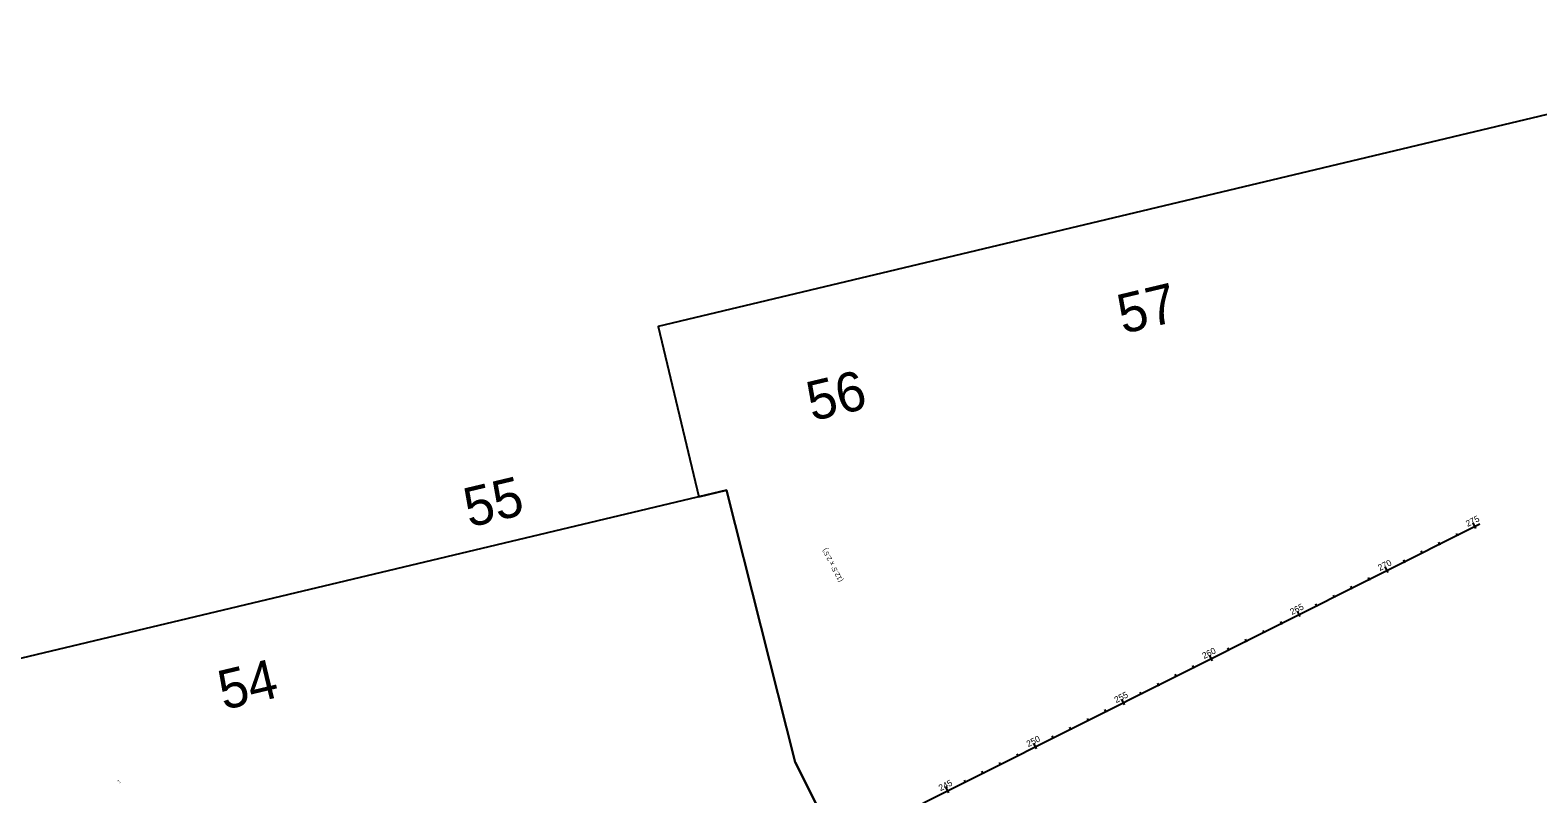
# Model space of a CAD drawing. Extents: x -5665 to 1997148, y 4 to 827579.
# Drawn here: x 1969802 to 1977472, y 804069 to 807957 of the extents above; entities that cross this region are included whole.
import ezdxf

# ---------------------------------------------------------------- set-up
doc = ezdxf.new("R2010")
doc.units = 0
for name, color, linetype in [('RD_HC_CL_Rel', 7, 'Continuous'), ('RD_HC_Data_Tic_Rel', 7, 'Continuous'), ('RD_HC_TX_Rel_Sta50', 7, 'Continuous'), ('RD_SHT_ShtClip', 7, 'Continuous'), ('RD_SHT_TX', 7, 'Continuous')]:
    doc.layers.add(name, color=color, linetype=linetype)

msp = doc.modelspace()

# ---------------------------------------------------------------- linework, layer by layer
at = {"layer": 'RD_HC_CL_Rel'}
msp.add_line((1971733.6, 802712.2), (1977177.4, 805443.1), dxfattribs=at)
at = {"layer": 'RD_HC_Data_Tic_Rel'}
for p, q in [((1977156.7, 805419.3), (1977142.3, 805447.9)), ((1976975.2, 805335), (1976968.1, 805349.3)), ((1977064.6, 805379.8), (1977057.4, 805394.1)), ((1976885.9, 805290.1), (1976878.7, 805304.4)), ((1976709.8, 805195.1), (1976695.4, 805223.7)), ((1976796.5, 805245.3), (1976789.3, 805259.6)), ((1976528.3, 805110.8), (1976521.1, 805125.1)), ((1976617.7, 805155.6), (1976610.5, 805169.9)), ((1976438.9, 805065.9), (1976431.8, 805080.2)), ((1976262.9, 804970.9), (1976248.5, 804999.5)), ((1976349.5, 805021.1), (1976342.4, 805035.4)), ((1976081.4, 804886.6), (1976074.2, 804900.9)), ((1976170.8, 804931.4), (1976163.6, 804945.7)), ((1975992, 804841.7), (1975984.8, 804856)), ((1975815.9, 804746.7), (1975801.6, 804775.3)), ((1975902.6, 804796.9), (1975895.5, 804811.2)), ((1975634.5, 804662.4), (1975627.3, 804676.7)), ((1975723.9, 804707.2), (1975716.7, 804721.5)), ((1975455.7, 804572.7), (1975448.5, 804587)), ((1975545.1, 804617.5), (1975537.9, 804631.8)), ((1975369, 804522.5), (1975354.7, 804551.1)), ((1975187.6, 804438.2), (1975180.4, 804452.5)), ((1975276.9, 804483), (1975269.8, 804497.3)), ((1975008.8, 804348.5), (1975001.6, 804362.8)), ((1975098.2, 804393.3), (1975091, 804407.6)), ((1974922.1, 804298.3), (1974907.8, 804326.9)), ((1974740.6, 804214), (1974733.5, 804228.3)), ((1974830, 804258.8), (1974822.9, 804273.1)), ((1974561.9, 804124.3), (1974554.7, 804138.6)), ((1974651.3, 804169.1), (1974644.1, 804183.4)), ((1974475.2, 804074.1), (1974460.8, 804102.7))]:
    msp.add_line(p, q, dxfattribs=at)
at = {"layer": 'RD_SHT_ShtClip'}
for points in [[(1973692.8, 804229.2), (1974094.7, 803428), (1974666.8, 802557.5), (1980293.7, 803871.4), (1979319.1, 807956.8), (1972996.5, 806448.5), (1973203.6, 805580.6), (1973344.3, 805614.1)], [(1967695.1, 802969), (1968000.2, 801689.9), (1968522.9, 801587.9), (1968575.1, 801281.2), (1968568.4, 800839.6), (1968542.7, 800594.7), (1968247.7, 800080.4), (1974570.3, 801588.8), (1974094.7, 803428), (1973692.8, 804229.2), (1973344.3, 805614.1), (1967347.3, 804183.5), (1967746.1, 803578.5)]]:
    msp.add_lwpolyline(points, close=True, dxfattribs=at)

# ---------------------------------------------------------------- texts
at = {"layer": 'RD_HC_TX_Rel_Sta50'}
for s, height, rotation, p in [('275', 32, 26.64085, (1977114.7, 805427.3)), ('270', 32, 26.64085, (1976667.7, 805203)), ('265', 32, 26.64085, (1976220.8, 804978.9)), ('260', 32, 26.64085, (1975773.8, 804754.6)), ('255', 32, 26.64085, (1975327, 804530.5)), ('250', 32, 26.64085, (1974880, 804306.2)), ('210', 8, 311.47902, (1970245.1, 804135.2)), ('245', 32, 26.64085, (1974433.1, 804082.1))]:
    msp.add_text(s, height=height, rotation=rotation, dxfattribs=at).set_placement(p)
at = {"layer": 'RD_SHT_TX'}
for s, height, rotation, p in [('57', 200, 13.41771, (1975360.9, 806409.3)), ('56', 200, 13.41771, (1973780, 805965.1)), ('55', 200, 13.41771, (1972035.9, 805424.2)), ("(12.5' x 2.5')", 25, 116.83168, (1973937.3, 805154.7)), ('54', 200, 13.41771, (1970786.2, 804494.5))]:
    msp.add_text(s, height=height, rotation=rotation, dxfattribs=at).set_placement(p)

doc.saveas('drawing.dxf')
